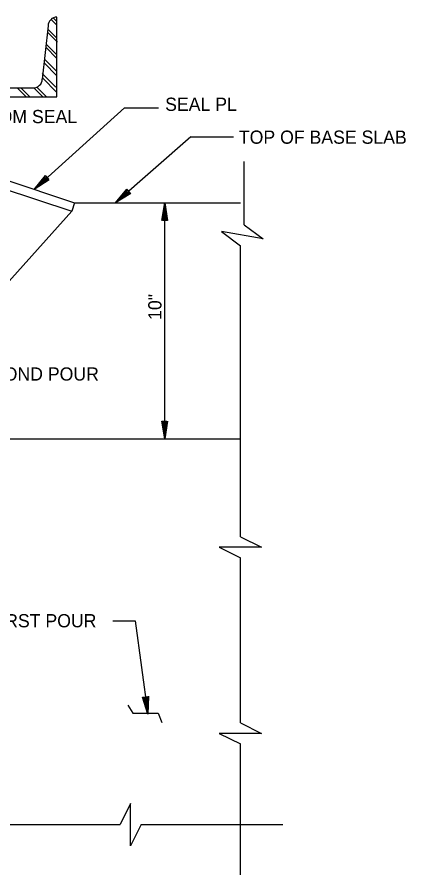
# Model space of a CAD drawing. Extents: x 0.1 to 13.5, y 0.1 to 9.5.
# Drawn here: x 4.919 to 6.292, y 3.728 to 6.759 of the extents above; entities that cross this region are included whole.
import ezdxf

# ---------------------------------------------------------------- set-up
doc = ezdxf.new("R2010")
doc.units = 0
for name, color, linetype in [('Level 13', 7, 'Continuous'), ('Level 25', 7, 'Continuous'), ('Level 50', 7, 'Continuous')]:
    doc.layers.add(name, color=color, linetype=linetype)

msp = doc.modelspace()

# ---------------------------------------------------------------- linework, layer by layer
at = {"layer": 'Level 13'}
for points in [[(5.7204, 6.0251), (5.7878, 5.9754), (5.6403, 6.0015), (5.7074, 5.9515)], [(5.7074, 4.9231), (5.7824, 4.8859), (5.6326, 4.8859), (5.7074, 4.8484)], [(5.7074, 4.2652), (5.7824, 4.228), (5.6326, 4.228), (5.7074, 4.1905)], [(5.3571, 3.9056), (5.3199, 3.8306), (5.3199, 3.9805), (5.2824, 3.9056)]]:
    msp.add_lwpolyline(points, dxfattribs=at)
at = {"layer": 'Level 25'}
for p, q in [((5.0596, 6.7307), (5.039, 6.7513)), ((5.0596, 6.7435), (5.0468, 6.7564)), ((5.0596, 6.4779), (5.0596, 6.7592)), ((5.0284, 6.7279), (5.0076, 6.5404)), ((5.0611, 6.671), (5.026, 6.7061)), ((5.0596, 6.6846), (5.0272, 6.717)), ((5.0596, 6.6129), (5.02, 6.6525)), ((5.0596, 6.6256), (5.0213, 6.664)), ((5.0596, 6.5667), (5.0154, 6.6109)), ((5.0596, 6.5514), (5.0139, 6.5972)), ((5.0554, 6.5121), (5.0071, 6.5603)), ((5.0596, 6.4927), (5.008, 6.5444)), ((3.893, 6.5092), (4.9763, 6.5092)), ((4.9493, 6.4783), (4.9198, 6.5078)), ((4.9633, 6.4779), (4.9321, 6.5092)), ((5.0083, 6.4783), (4.9787, 6.5078)), ((5.0224, 6.4779), (4.9888, 6.5115)), ((3.8096, 6.4779), (5.0596, 6.4779)), ((5.2982, 6.4386), (4.9795, 6.1502)), ((5.2982, 6.4386), (5.4181, 6.4386)), ((5.5319, 6.3361), (5.2669, 6.1027)), ((5.5319, 6.3361), (5.6832, 6.3361)), ((5.7204, 6.0251), (5.7204, 6.249)), ((4.8721, 6.186), (5.1221, 6.1027)), ((4.8623, 6.1564), (5.1123, 6.073)), ((5.1221, 6.1027), (5.1123, 6.073)), ((5.1221, 6.1027), (5.7074, 6.1027)), ((5.4403, 5.2694), (5.4403, 6.1027)), ((5.1123, 6.073), (4.748, 5.6685)), ((5.7074, 4.9231), (5.7074, 5.9515)), ((1.8741, 5.2694), (5.7074, 5.2694)), ((5.7074, 4.2652), (5.7074, 4.8484)), ((5.2569, 4.6256), (5.3354, 4.6256)), ((5.3354, 4.6256), (5.3807, 4.2957)), ((5.3103, 4.3271), (5.3281, 4.2989)), ((5.3281, 4.2989), (5.4172, 4.2989)), ((5.4172, 4.2989), (5.4306, 4.2664)), ((5.7074, 3.7279), (5.7074, 4.1905)), ((4.3282, 3.9056), (5.2824, 3.9056)), ((5.3571, 3.9056), (5.858, 3.9056))]:
    msp.add_line(p, q, dxfattribs=at)
for centre, start, end in [((5.0596, 6.7279), 90, 180), ((4.9763, 6.5404), 270, 0)]:
    msp.add_arc(centre, 0.0313, start, end, dxfattribs=at)
at = {"layer": 'Level 50'}
for p, q in [((4.9924, 6.1619), (4.9924, 6.1619)), ((4.9795, 6.1502), (4.9795, 6.1502)), ((5.2669, 6.1027), (5.2669, 6.1027)), ((5.2799, 6.1142), (5.2799, 6.1142)), ((5.4403, 6.1027), (5.4403, 6.1027)), ((5.4403, 6.0854), (5.4403, 6.0854)), ((5.4403, 5.2867), (5.4403, 5.2867)), ((5.4403, 5.2694), (5.4403, 5.2694)), ((5.3783, 4.3129), (5.3783, 4.3129)), ((5.3807, 4.2957), (5.3807, 4.2957))]:
    msp.add_line(p, q, dxfattribs=at)
for points in [[(5.0327, 6.1844), (4.9795, 6.1502), (5.0188, 6.1997), (5.0307, 6.1866), (4.9924, 6.1619), (5.0191, 6.1955), (5.0267, 6.1871), (5.0048, 6.173), (5.0193, 6.1912), (5.0225, 6.1877), (5.0176, 6.1847)], [(5.3205, 6.1361), (5.2669, 6.1027), (5.3069, 6.1517), (5.3186, 6.1384), (5.2799, 6.1142), (5.3071, 6.1474), (5.3146, 6.1389), (5.2924, 6.1252), (5.3073, 6.1431), (5.3104, 6.1396), (5.3055, 6.1366)], [(5.4299, 6.0404), (5.4403, 6.1027), (5.4506, 6.0404), (5.4329, 6.0404), (5.4403, 6.0854), (5.4473, 6.043), (5.4359, 6.043), (5.4403, 6.0687), (5.4439, 6.0457), (5.4393, 6.0457), (5.4403, 6.0514)], [(5.4506, 5.3317), (5.4403, 5.2694), (5.4299, 5.3317), (5.4476, 5.3317), (5.4403, 5.2867), (5.4333, 5.329), (5.4446, 5.329), (5.4403, 5.3034), (5.4366, 5.3264), (5.4413, 5.3264), (5.4403, 5.3207)], [(5.3824, 4.3589), (5.3807, 4.2957), (5.362, 4.3561), (5.3795, 4.3585), (5.3783, 4.3129), (5.3656, 4.3539), (5.3769, 4.3554), (5.3761, 4.3294), (5.3693, 4.3517), (5.3739, 4.3523), (5.3737, 4.3466)]]:
    msp.add_lwpolyline(points, dxfattribs=at)

# ---------------------------------------------------------------- texts
at = {"layer": 'Level 25'}
for s, height, p in [('SEAL PL', 0.04667, (5.4417, 6.428)), ('BOTTOM SEAL', 0.046667, (4.6871, 6.3845)), ('TOP OF BASE SLAB', 0.046667, (5.7021, 6.3117)), ('SECOND POUR', 0.046667, (4.7431, 5.4747)), ('FIRST POUR', 0.04667, (4.8212, 4.6027))]:
    msp.add_text(s, height=height, dxfattribs=at).set_placement(p)
msp.add_text('10"', height=0.04667, rotation=90, dxfattribs=at).set_placement((5.4287, 5.6892))

doc.saveas('drawing.dxf')
